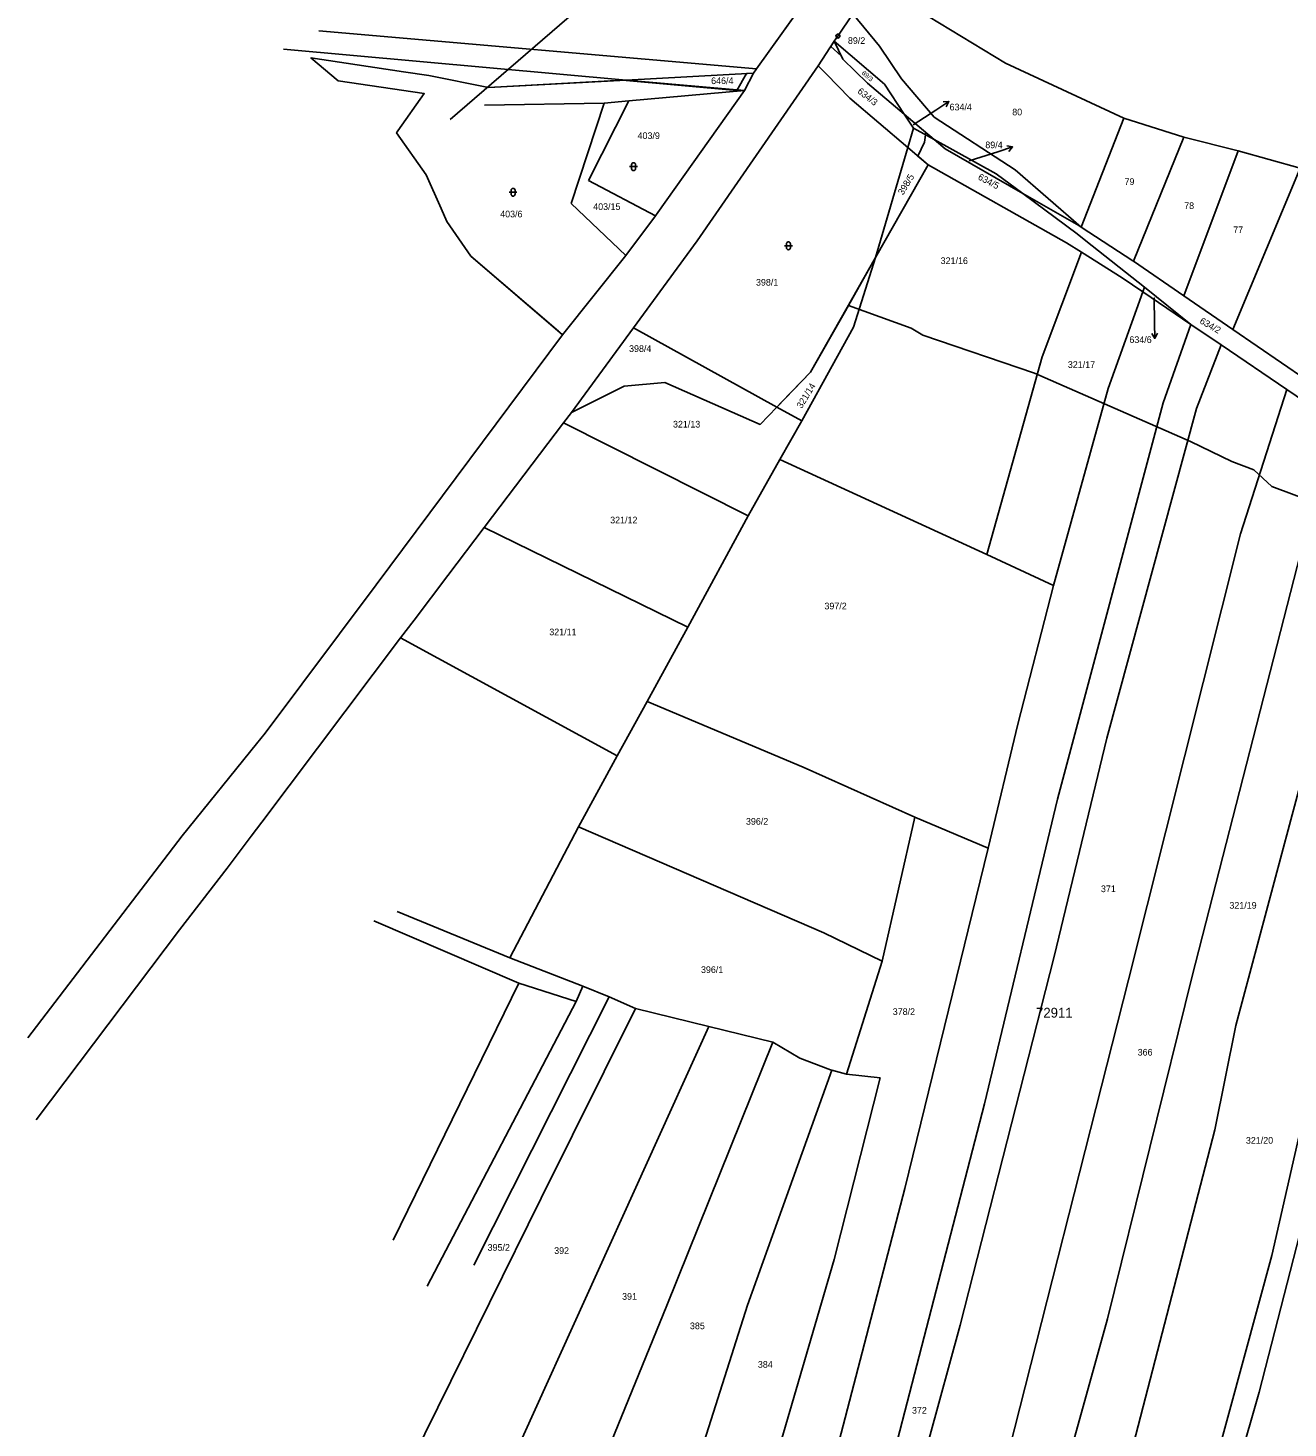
# Model space of a CAD drawing. Extents: x -743888 to -742027, y -1128394 to -1126768.
# Drawn here: x -743887.8 to -743566.3, y -1127677.1 to -1127319.9 of the extents above; entities that cross this region are included whole.
import ezdxf

# ---------------------------------------------------------------- set-up
doc = ezdxf.new("R2010")
doc.units = 0
for name, color, linetype in [('Vrstva 1', 7, 'Continuous'), ('Vrstva 12', 7, 'Continuous'), ('Vrstva 16', 7, 'Continuous'), ('Vrstva 18', 7, 'Continuous'), ('Vrstva 24', 7, 'Continuous'), ('Vrstva 25', 7, 'Continuous'), ('Vrstva 52', 7, 'Continuous'), ('Vrstva 53', 7, 'Continuous'), ('Vrstva 6', 7, 'Continuous')]:
    doc.layers.add(name, color=color, linetype=linetype)

msp = doc.modelspace()

# ---------------------------------------------------------------- linework, layer by layer
at = {"layer": 'Vrstva 1'}
for points in [[(-743701.89, -1127330.35), (-743691.32, -1127315.58)], [(-743681.13, -1127321.96), (-743677.33, -1127316.28)], [(-743682.05, -1127323.29), (-743681.13, -1127321.96)], [(-743686.17, -1127329.52), (-743682.05, -1127323.29)], [(-743682.05, -1127323.29), (-743679.84, -1127327.83)], [(-743717.04, -1127374.23), (-743686.17, -1127329.52)], [(-743686.17, -1127329.52), (-743684.1, -1127331.61)], [(-743679.84, -1127327.83), (-743673.62, -1127333.98)], [(-743705.01, -1127335.87), (-743702.67, -1127331.44)], [(-743702.67, -1127331.44), (-743701.89, -1127330.35)], [(-743684.1, -1127331.61), (-743678.08, -1127337.84)], [(-743734.53, -1127338.5), (-743705.01, -1127335.87)], [(-743727.05, -1127366.98), (-743705.01, -1127335.87)], [(-743673.62, -1127333.98), (-743664.22, -1127341.91)], [(-743771.3, -1127339.6), (-743740.8, -1127339.06)], [(-743749.17, -1127364.64), (-743740.8, -1127339.06)], [(-743740.8, -1127339.06), (-743734.53, -1127338.5)], [(-743678.08, -1127337.84), (-743663.32, -1127350.36)], [(-743664.22, -1127341.91), (-743656.57, -1127348.37)], [(-743663.32, -1127350.36), (-743658.11, -1127354.78)], [(-743656.57, -1127348.37), (-743653.73, -1127350.76)], [(-743653.73, -1127350.76), (-743633.94, -1127362.12)], [(-743671.53, -1127378.48), (-743658.11, -1127354.78)], [(-743658.11, -1127354.78), (-743622.79, -1127374.68)], [(-743633.94, -1127362.12), (-743619.65, -1127370.33)], [(-743749.17, -1127364.64), (-743735.23, -1127377.99)], [(-743735.23, -1127377.99), (-743727.68, -1127367.83)], [(-743727.68, -1127367.83), (-743727.05, -1127366.98)], [(-743619.65, -1127370.33), (-743619.02, -1127370.74)], [(-743619.02, -1127370.74), (-743605.84, -1127379.32)], [(-743733.3, -1127396.4), (-743717.04, -1127374.23)], [(-743622.79, -1127374.68), (-743618.94, -1127377.12)], [(-743774.81, -1127378.12), (-743751.42, -1127398.16)], [(-743751.42, -1127398.16), (-743735.23, -1127377.99)], [(-743688.11, -1127407.75), (-743671.53, -1127378.48)], [(-743618.94, -1127377.12), (-743608.59, -1127383.67)], [(-743605.84, -1127379.32), (-743605.72, -1127379.4)], [(-743605.72, -1127379.4), (-743592.83, -1127388.25)], [(-743608.59, -1127383.67), (-743603.32, -1127387.24)], [(-743603.32, -1127387.24), (-743591.07, -1127395.53)], [(-743592.83, -1127388.25), (-743580.36, -1127396.81)], [(-743749.15, -1127418.02), (-743733.3, -1127396.4)], [(-743591.07, -1127395.53), (-743583.33, -1127400.78)], [(-743580.36, -1127396.81), (-743555.5, -1127413.88)], [(-743798.95, -1127461.99), (-743751.42, -1127398.16)], [(-743583.33, -1127400.78), (-743566.53, -1127412.16)], [(-743696.72, -1127416.64), (-743688.11, -1127407.75)], [(-743749.15, -1127418.02), (-743735.67, -1127411.25)], [(-743735.67, -1127411.25), (-743725.34, -1127410.33)], [(-743725.34, -1127410.33), (-743700.98, -1127421.05)], [(-743566.53, -1127412.16), (-743552.04, -1127421.98)], [(-743751.15, -1127420.66), (-743749.15, -1127418.02)], [(-743700.98, -1127421.05), (-743696.72, -1127416.64)], [(-743771.38, -1127447.34), (-743751.15, -1127420.66)]]:
    msp.add_lwpolyline(points, dxfattribs=at)
at = {"layer": 'Vrstva 12'}
msp.add_lwpolyline([(-743780.05, -1127343.28), (-743726.15, -1127296.67)], dxfattribs=at)
at = {"layer": 'Vrstva 16'}
for p, q in [((-743654.29, -1127338.76), (-743652.79, -1127338.67)), ((-743638, -1127349.94), (-743636.53, -1127350.26)), ((-743599.54, -1127397.79), (-743600.28, -1127399.1))]:
    msp.add_line(p, q, dxfattribs=at)
for points in [[(-743656.14, -1127340.86), (-743652.79, -1127338.67), (-743653.47, -1127340.01)], [(-743661.92, -1127344.63), (-743656.14, -1127340.86)], [(-743647.59, -1127353.8), (-743640.34, -1127351.48)], [(-743640.34, -1127351.48), (-743636.53, -1127350.26), (-743637.54, -1127351.37)], [(-743600.38, -1127388.76), (-743600.32, -1127395.1)], [(-743600.32, -1127395.1), (-743600.28, -1127399.1), (-743601.04, -1127397.81)]]:
    msp.add_lwpolyline(points, dxfattribs=at)
at = {"layer": 'Vrstva 24'}
msp.add_line((-743681.18, -1127321.96), (-743681.08, -1127321.96), dxfattribs=at)
msp.add_circle((-743681.13, -1127321.96), 0.499, dxfattribs=at)
at = {"layer": 'Vrstva 25'}
for p, q in [((-743733.78, -1127354.78), (-743733.78, -1127355.78)), ((-743732.78, -1127354.78), (-743732.78, -1127355.78)), ((-743734.28, -1127355.28), (-743732.28, -1127355.28)), ((-743765.03, -1127361.81), (-743763.03, -1127361.81)), ((-743764.53, -1127361.31), (-743764.53, -1127362.31)), ((-743763.53, -1127361.31), (-743763.53, -1127362.31)), ((-743694.76, -1127375.46), (-743692.76, -1127375.46)), ((-743694.26, -1127374.96), (-743694.26, -1127375.96)), ((-743693.26, -1127374.96), (-743693.26, -1127375.96))]:
    msp.add_line(p, q, dxfattribs=at)
for centre, start, end in [((-743733.28, -1127354.78), 0, 180), ((-743733.28, -1127355.78), 180, 0), ((-743764.03, -1127361.31), 0, 180), ((-743764.03, -1127362.31), 180, 0), ((-743693.76, -1127374.96), 0, 180), ((-743693.76, -1127375.96), 180, 0)]:
    msp.add_arc(centre, 0.5, start, end, dxfattribs=at)
at = {"layer": 'Vrstva 52'}
for points in [[(-743792.03, -1127331.05), (-743785.55, -1127332.01), (-743770.32, -1127335.04), (-743736.1, -1127333.22), (-743706.94, -1127335.88), (-743704.43, -1127331.53), (-743702.67, -1127331.44), (-743701.89, -1127330.35), (-743693.05, -1127318), (-743691.32, -1127315.58), (-743689.23, -1127312.32), (-743658.6, -1127264.57), (-743647.27, -1127248.07), (-743646.21, -1127246.53)], [(-743678.44, -1127390.67), (-743671.53, -1127378.48), (-743658.11, -1127354.78), (-743660.69, -1127352.59), (-743659, -1127349), (-743658.7, -1127346.57), (-743664.22, -1127341.91), (-743673.62, -1127333.98), (-743679.84, -1127327.83), (-743680.26, -1127326.97), (-743682.93, -1127324.62), (-743682.05, -1127323.29), (-743681.13, -1127321.96), (-743677.33, -1127316.28), (-743672.05, -1127308.38), (-743649.24, -1127274.28), (-743635.53, -1127253.78), (-743632.18, -1127248.58)], [(-743887.83, -1127577.55), (-743848.49, -1127526.01), (-743829.49, -1127502.59), (-743827.26, -1127499.85), (-743798.95, -1127461.99), (-743751.42, -1127398.16), (-743752.45, -1127397.28), (-743774.81, -1127378.12), (-743780.97, -1127369.29), (-743782.41, -1127365.99), (-743786.2, -1127357.34), (-743793.75, -1127346.62), (-743793.43, -1127346.17), (-743786.7, -1127336.65), (-743808.63, -1127333.42), (-743815.63, -1127327.55), (-743792.03, -1127331.05)], [(-743885.71, -1127598.47), (-743849.15, -1127549.98), (-743837.01, -1127534.27), (-743830.84, -1127526.09), (-743828.18, -1127522.56), (-743792.74, -1127475.54), (-743789.29, -1127470.96), (-743780.71, -1127459.64), (-743771.38, -1127447.34), (-743751.15, -1127420.66), (-743749.15, -1127418.02), (-743735.67, -1127411.25), (-743725.34, -1127410.33), (-743700.98, -1127421.05), (-743696.72, -1127416.64), (-743695.49, -1127415.37), (-743688.11, -1127407.75), (-743679.22, -1127392.05), (-743678.44, -1127390.67)], [(-743678.44, -1127390.67), (-743662.44, -1127396.5), (-743659.44, -1127398.25), (-743631, -1127408), (-743591.13, -1127425.38), (-743580.56, -1127430.5), (-743575, -1127432.63), (-743570.38, -1127436.88), (-743554.69, -1127442.75)]]:
    msp.add_lwpolyline(points, dxfattribs=at)
at = {"layer": 'Vrstva 6'}
for points in [[(-743672.05, -1127308.38), (-743638.39, -1127328.87)], [(-743677.33, -1127316.28), (-743670.54, -1127324.52)], [(-743813.6, -1127320.66), (-743701.89, -1127330.35)], [(-743822.64, -1127325.34), (-743735.17, -1127333.17)], [(-743682.05, -1127323.29), (-743669.28, -1127334.27)], [(-743670.54, -1127324.52), (-743664.92, -1127332.9)], [(-743638.39, -1127328.87), (-743608.18, -1127342.94)], [(-743770.32, -1127335.04), (-743735.17, -1127333.17)], [(-743735.17, -1127333.17), (-743702.67, -1127331.44)], [(-743735.17, -1127333.17), (-743705.01, -1127335.87)], [(-743664.92, -1127332.9), (-743656.54, -1127342.61)], [(-743669.28, -1127334.27), (-743664.22, -1127341.91)], [(-743744.74, -1127358.84), (-743734.53, -1127338.5)], [(-743664.22, -1127341.91), (-743661.88, -1127345.44)], [(-743656.54, -1127342.61), (-743635.91, -1127356.08)], [(-743619.02, -1127370.74), (-743608.18, -1127342.94)], [(-743608.18, -1127342.94), (-743592.88, -1127347.72)], [(-743663.32, -1127350.36), (-743661.88, -1127345.44)], [(-743661.88, -1127345.44), (-743656.57, -1127348.37)], [(-743605.72, -1127379.4), (-743592.88, -1127347.72)], [(-743592.88, -1127347.72), (-743578.94, -1127351.24)], [(-743671.53, -1127378.48), (-743663.32, -1127350.36)], [(-743656.57, -1127348.37), (-743640.77, -1127357.07)], [(-743592.83, -1127388.25), (-743578.94, -1127351.24)], [(-743578.94, -1127351.24), (-743563.19, -1127355.67)], [(-743640.77, -1127357.07), (-743633.94, -1127362.12)], [(-743635.91, -1127356.08), (-743619.02, -1127370.74)], [(-743580.36, -1127396.81), (-743563.19, -1127355.67)], [(-743744.74, -1127358.84), (-743727.68, -1127367.83)], [(-743633.94, -1127362.12), (-743620.04, -1127372.41)], [(-743620.04, -1127372.41), (-743617.83, -1127374.17)], [(-743617.83, -1127374.17), (-743602.9, -1127386.07)], [(-743677.11, -1127396.22), (-743671.53, -1127378.48)], [(-743628.97, -1127403.83), (-743618.94, -1127377.12)], [(-743603.32, -1127387.24), (-743602.9, -1127386.07)], [(-743602.9, -1127386.07), (-743591.07, -1127395.53)], [(-743612.17, -1127411.89), (-743603.32, -1127387.24)], [(-743733.3, -1127396.4), (-743696.72, -1127416.64)], [(-743690.34, -1127420.17), (-743677.11, -1127396.22)], [(-743598.16, -1127415.52), (-743591.07, -1127395.53)], [(-743589.64, -1127417.03), (-743583.33, -1127400.78)], [(-743643.11, -1127454.25), (-743628.97, -1127403.83)], [(-743626.1, -1127462.14), (-743612.17, -1127411.89)], [(-743578.37, -1127448.95), (-743566.53, -1127412.16)], [(-743625.08, -1127516.64), (-743598.16, -1127415.52)], [(-743696.72, -1127416.64), (-743690.34, -1127420.17)], [(-743612.49, -1127501.11), (-743589.64, -1127417.03)], [(-743751.15, -1127420.66), (-743704.03, -1127444.35)], [(-743695.91, -1127430.01), (-743690.34, -1127420.17)], [(-743704.03, -1127444.35), (-743695.91, -1127430.01)], [(-743695.91, -1127430.01), (-743643.11, -1127454.25)], [(-743719.41, -1127472.79), (-743704.03, -1127444.35)], [(-743771.38, -1127447.34), (-743719.41, -1127472.79)], [(-743590.72, -1127561.84), (-743561.28, -1127447)], [(-743606.94, -1127562.76), (-743578.37, -1127448.95)], [(-743579.58, -1127574.43), (-743546.31, -1127450.09)], [(-743643.11, -1127454.25), (-743626.1, -1127462.14)], [(-743635.23, -1127497.57), (-743626.1, -1127462.14)], [(-743729.83, -1127491.77), (-743719.41, -1127472.79)], [(-743792.74, -1127475.54), (-743737.45, -1127505.65)], [(-743737.45, -1127505.65), (-743729.83, -1127491.77)], [(-743729.83, -1127491.77), (-743689.97, -1127508.53)], [(-743642.79, -1127529.21), (-743635.23, -1127497.57)], [(-743625.94, -1127556.86), (-743612.49, -1127501.11)], [(-743747.3, -1127523.7), (-743737.45, -1127505.65)], [(-743689.97, -1127508.53), (-743661.46, -1127521.24)], [(-743643.68, -1127594.43), (-743625.08, -1127516.64)], [(-743669.86, -1127557.99), (-743661.46, -1127521.24)], [(-743661.46, -1127521.24), (-743642.79, -1127529.21)], [(-743764.87, -1127557.13), (-743747.3, -1127523.7)], [(-743747.3, -1127523.7), (-743684.68, -1127550.8)], [(-743664.09, -1127615.99), (-743642.79, -1127529.21)], [(-743799.59, -1127547.73), (-743762.59, -1127563.64)], [(-743793.58, -1127545.38), (-743764.87, -1127557.13)], [(-743684.68, -1127550.8), (-743669.86, -1127557.99)], [(-743764.87, -1127557.13), (-743746.22, -1127564.41)], [(-743678.91, -1127586.83), (-743669.86, -1127557.99)], [(-743649.9, -1127650.85), (-743625.94, -1127556.86)], [(-743612.33, -1127649.25), (-743590.72, -1127561.84)], [(-743794.63, -1127629.19), (-743762.59, -1127563.64)], [(-743762.59, -1127563.64), (-743747.9, -1127568.32)], [(-743747.9, -1127568.32), (-743746.22, -1127564.41)], [(-743746.22, -1127564.41), (-743739.51, -1127567.07)], [(-743640.25, -1127693.79), (-743606.94, -1127562.76)], [(-743570.37, -1127633.12), (-743554.73, -1127564.38)], [(-743785.95, -1127640.98), (-743747.9, -1127568.32)], [(-743774.01, -1127635.57), (-743739.51, -1127567.07)], [(-743739.51, -1127567.07), (-743732.8, -1127570.06)], [(-743756.85, -1127618.5), (-743732.8, -1127570.06)], [(-743732.8, -1127570.06), (-743714.07, -1127574.65)], [(-743777.04, -1127713.53), (-743714.07, -1127574.65)], [(-743714.07, -1127574.65), (-743697.73, -1127578.65)], [(-743584.91, -1127601.01), (-743579.58, -1127574.43)], [(-743724.77, -1127645.91), (-743697.73, -1127578.65)], [(-743697.73, -1127578.65), (-743690.83, -1127582.75)], [(-743690.83, -1127582.75), (-743683.02, -1127585.74)], [(-743704.24, -1127645.83), (-743682.66, -1127585.84)], [(-743683.02, -1127585.74), (-743682.66, -1127585.84)], [(-743682.66, -1127585.84), (-743678.91, -1127586.83)], [(-743678.91, -1127586.83), (-743670.32, -1127587.74)], [(-743682.11, -1127634.16), (-743670.32, -1127587.74)], [(-743673.31, -1127708.75), (-743643.68, -1127594.43)], [(-743612.44, -1127707.12), (-743584.91, -1127601.01)], [(-743796.4, -1127698.58), (-743756.85, -1127618.5)], [(-743695.53, -1127736.94), (-743664.09, -1127615.99)], [(-743573.61, -1127667.99), (-743561.74, -1127621.6)], [(-743599.16, -1127738.75), (-743570.37, -1127633.12)], [(-743699.9, -1127694.98), (-743682.11, -1127634.16)], [(-743756.8, -1127724.26), (-743724.77, -1127645.91)], [(-743730.37, -1127728.24), (-743704.24, -1127645.83)], [(-743673.66, -1127737.68), (-743649.9, -1127650.85)], [(-743636.86, -1127737.44), (-743612.33, -1127649.25)], [(-743594.04, -1127739.28), (-743573.61, -1127667.99)]]:
    msp.add_lwpolyline(points, dxfattribs=at)

# ---------------------------------------------------------------- texts
at = {"layer": 'Vrstva 16'}
for s, p in [('634/4', (-743652.63, -1127340.92)), ('89/4', (-743643.51, -1127350.57)), ('634/6', (-743606.74, -1127400.28))]:
    msp.add_text(s, height=1.7, dxfattribs=at).set_placement(p)
at = {"layer": 'Vrstva 18'}
for s, height, p in [('89/2', 1.7, (-743678.57, -1127323.95)), ('646/4', 1.7, (-743713.48, -1127334.21)), ('80', 1.7, (-743636.64, -1127342.19)), ('403/9', 1.7, (-743732.26, -1127348.22)), ('634/4', 0.1, (-743661.92, -1127344.63)), ('89/4', 0.1, (-743647.59, -1127353.8)), ('79', 1.7, (-743607.98, -1127359.95)), ('403/15', 1.7, (-743743.58, -1127366.32)), ('78', 1.7, (-743592.75, -1127366.09)), ('403/6', 1.7, (-743767.32, -1127368.21)), ('77', 1.7, (-743580.24, -1127372.24)), ('321/16', 1.7, (-743654.91, -1127380.13)), ('398/1', 1.7, (-743702.04, -1127385.63)), ('634/6', 0.1, (-743600.38, -1127388.76)), ('398/4', 1.7, (-743734.43, -1127402.55)), ('321/17', 1.7, (-743622.44, -1127406.63)), ('321/13', 1.7, (-743723.22, -1127421.84)), ('321/12', 1.7, (-743739.25, -1127446.3)), ('397/2', 1.7, (-743684.57, -1127468.24)), ('321/11', 1.7, (-743754.79, -1127474.85)), ('396/2', 1.7, (-743704.6, -1127523.19)), ('371', 1.7, (-743614, -1127540.4)), ('321/19', 1.7, (-743581.22, -1127544.62)), ('396/1', 1.7, (-743716.08, -1127561.02)), ('378/2', 1.7, (-743667.13, -1127571.73)), ('366', 1.7, (-743604.63, -1127582.1)), ('321/20', 1.7, (-743577.01, -1127604.59)), ('395/2', 1.7, (-743770.53, -1127631.91)), ('392', 1.7, (-743753.54, -1127632.71)), ('391', 1.7, (-743736.21, -1127644.42)), ('385', 1.7, (-743718.89, -1127651.92)), ('384', 1.7, (-743701.56, -1127661.76)), ('372', 1.7, (-743662.23, -1127673.47))]:
    msp.add_text(s, height=height, dxfattribs=at).set_placement(p)
for s, height, rotation, p in [('89/3', 1.19, 318.8697, (-743675.17, -1127331.54)), ('634/3', 1.7, 321.9699, (-743676.3, -1127336.34)), ('398/5', 1.7, 58.6735, (-743664.5, -1127362.66)), ('634/5', 1.7, 332.0718, (-743645.56, -1127358.44)), ('634/2', 1.7, 330.1789, (-743588.96, -1127395.13)), ('321/14', 1.7, 58.6411, (-743690.36, -1127417.12))]:
    msp.add_text(s, height=height, rotation=rotation, dxfattribs=at).set_placement(p)
at = {"layer": 'Vrstva 53'}
msp.add_text('72911', height=2.5, dxfattribs=at).set_placement((-743630.55, -1127572.41))

doc.saveas('drawing.dxf')
